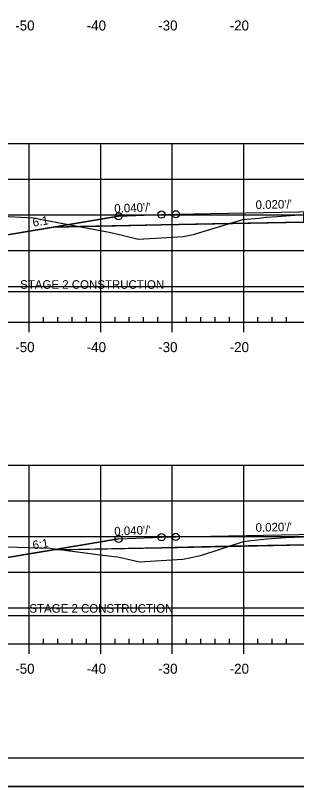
# Model space of a CAD drawing. Extents: x 1365647 to 1367999, y 387113 to 400173.
# Drawn here: x 1365842.2 to 1365881.5, y 387372.7 to 387480.6 of the extents above; entities that cross this region are included whole.
import ezdxf

# ---------------------------------------------------------------- set-up
doc = ezdxf.new("R2010")
doc.units = 0
for name, color, linetype in [('R_Alt Surface', 7, 'Continuous'), ('R_Axis', 7, 'Continuous'), ('R_Axis Annot', 7, 'Continuous'), ('R_Border', 7, 'Continuous'), ('R_Contours', 7, 'Continuous'), ('R_Exist Surface', 7, 'Continuous'), ('R_Fin Surface', 7, 'Continuous'), ('R_Fin Surface Annot', 7, 'Continuous'), ('R_Grid', 7, 'Continuous'), ('R_No Plot', 7, 'Continuous'), ('R_Proposed Const Limits', 7, 'Continuous'), ('R_Water', 7, 'Continuous')]:
    doc.layers.add(name, color=color, linetype=linetype)

msp = doc.modelspace()

# ---------------------------------------------------------------- linework, layer by layer
at = {"layer": 'R_Alt Surface'}
for points in [[(1365847.47, 387451.01), (1365862.59, 387451.32), (1365882.53, 387451.72), (1365882.53, 387453), (1365894.09, 387453.23), (1365906.15, 387452.99), (1365906.15, 387451.71), (1365925.59, 387451.32), (1365940.72, 387451.01)], [(1365847.47, 387405.86), (1365862.59, 387406.16), (1365882.72, 387406.56), (1365882.72, 387407.85), (1365894.09, 387408.08), (1365906.2, 387407.84), (1365906.2, 387406.55), (1365925.59, 387406.16), (1365940.72, 387405.86)]]:
    msp.add_lwpolyline(points, dxfattribs=at)
at = {"layer": 'R_Axis'}
for p, q in [((1365749.09, 387437.72), (1366039.09, 387437.72)), ((1365844.09, 387436.32), (1365844.09, 387437.72)), ((1365846.09, 387437.72), (1365846.09, 387438.42)), ((1365848.09, 387437.72), (1365848.09, 387438.42)), ((1365850.09, 387437.72), (1365850.09, 387438.42)), ((1365852.09, 387437.72), (1365852.09, 387438.42)), ((1365854.09, 387436.32), (1365854.09, 387437.72)), ((1365856.09, 387437.72), (1365856.09, 387438.42)), ((1365858.09, 387437.72), (1365858.09, 387438.42)), ((1365860.09, 387437.72), (1365860.09, 387438.42)), ((1365862.09, 387437.72), (1365862.09, 387438.42)), ((1365864.09, 387436.32), (1365864.09, 387437.72)), ((1365866.09, 387437.72), (1365866.09, 387438.42)), ((1365868.09, 387437.72), (1365868.09, 387438.42)), ((1365870.09, 387437.72), (1365870.09, 387438.42)), ((1365872.09, 387437.72), (1365872.09, 387438.42)), ((1365874.09, 387436.32), (1365874.09, 387437.72)), ((1365876.09, 387437.72), (1365876.09, 387438.42)), ((1365878.09, 387437.72), (1365878.09, 387438.42)), ((1365880.09, 387437.72), (1365880.09, 387438.42)), ((1365846.09, 387392.72), (1365846.09, 387393.42)), ((1365848.09, 387392.72), (1365848.09, 387393.42)), ((1365850.09, 387392.72), (1365850.09, 387393.42)), ((1365852.09, 387392.72), (1365852.09, 387393.42)), ((1365856.09, 387392.72), (1365856.09, 387393.42)), ((1365858.09, 387392.72), (1365858.09, 387393.42)), ((1365860.09, 387392.72), (1365860.09, 387393.42)), ((1365862.09, 387392.72), (1365862.09, 387393.42)), ((1365866.09, 387392.72), (1365866.09, 387393.42)), ((1365868.09, 387392.72), (1365868.09, 387393.42)), ((1365870.09, 387392.72), (1365870.09, 387393.42)), ((1365872.09, 387392.72), (1365872.09, 387393.42)), ((1365876.09, 387392.72), (1365876.09, 387393.42)), ((1365878.09, 387392.72), (1365878.09, 387393.42)), ((1365880.09, 387392.72), (1365880.09, 387393.42)), ((1365749.09, 387392.72), (1366039.09, 387392.72)), ((1365844.09, 387391.32), (1365844.09, 387392.72)), ((1365854.09, 387391.32), (1365854.09, 387392.72)), ((1365864.09, 387391.32), (1365864.09, 387392.72)), ((1365874.09, 387391.32), (1365874.09, 387392.72))]:
    msp.add_line(p, q, dxfattribs=at)
at = {"layer": 'R_Border'}
msp.add_line((1366052.27, 387376.72), (1365736.09, 387376.72), dxfattribs=at)
at = {"layer": 'R_Contours'}
for points in [[(1365872.13, 387451.51), (1365873.96, 387452.06), (1365876.25, 387452.28), (1365877.22, 387452.39), (1365878.77, 387452.49), (1365882.44, 387452.78), (1365882.53, 387452.78), (1365882.53, 387451.72)], [(1365824.59, 387452.2), (1365830.65, 387452.34), (1365833.44, 387452.49), (1365834.4, 387452.59), (1365841.21, 387452.51), (1365844.62, 387452.32), (1365846.82, 387451.9), (1365851.12, 387451.09), (1365847.47, 387451.01), (1365834.59, 387448.87)], [(1365851.12, 387451.09), (1365855.28, 387450.3), (1365857.08, 387449.86), (1365859.33, 387449.34), (1365863.34, 387449.57), (1365865.63, 387449.69), (1365867.25, 387450.03), (1365867.28, 387450.04), (1365867.33, 387450.05), (1365872.13, 387451.51), (1365862.59, 387451.32)], [(1365872.04, 387406.35), (1365874.05, 387407.01), (1365875.12, 387407.16), (1365877.33, 387407.4), (1365879.94, 387407.56), (1365882.36, 387407.68), (1365882.72, 387407.7), (1365882.72, 387406.56)], [(1365826.33, 387406.46), (1365831.54, 387406.34), (1365835.37, 387406.39), (1365837.51, 387406.45), (1365840.88, 387406.3), (1365847, 387406.09), (1365848.63, 387405.88), (1365847.47, 387405.86), (1365834.59, 387403.71)], [(1365848.63, 387405.88), (1365854.38, 387405.13), (1365856.43, 387404.87), (1365857.71, 387404.58), (1365859.51, 387404.18), (1365864.8, 387404.49), (1365865.59, 387404.53), (1365866.57, 387404.74), (1365868.18, 387405.09), (1365870.11, 387405.71), (1365872.04, 387406.35), (1365862.59, 387406.16)]]:
    msp.add_lwpolyline(points, close=True, dxfattribs=at)
at = {"layer": 'R_Exist Surface'}
for points in [[(1365841.21, 387452.51), (1365844.62, 387452.32), (1365846.82, 387451.9), (1365855.28, 387450.3), (1365857.08, 387449.86), (1365859.33, 387449.34), (1365863.34, 387449.57), (1365865.63, 387449.69), (1365867.25, 387450.03), (1365867.28, 387450.04), (1365867.33, 387450.05), (1365873.96, 387452.06), (1365876.25, 387452.28), (1365877.22, 387452.39), (1365878.77, 387452.49), (1365882.44, 387452.78)], [(1365840.88, 387406.3), (1365847, 387406.09), (1365854.38, 387405.13), (1365856.43, 387404.87), (1365857.71, 387404.58), (1365859.51, 387404.18), (1365864.8, 387404.49), (1365865.59, 387404.53), (1365866.57, 387404.74), (1365868.18, 387405.09), (1365870.11, 387405.71), (1365874.05, 387407.01), (1365875.12, 387407.16), (1365877.33, 387407.4), (1365879.94, 387407.56), (1365882.36, 387407.68)]]:
    msp.add_lwpolyline(points, dxfattribs=at)
at = {"layer": 'R_Fin Surface'}
for points in [[(1365824.59, 387452.2), (1365834.59, 387448.87), (1365847.47, 387451.01), (1365856.59, 387452.53), (1365862.59, 387452.77), (1365864.59, 387452.81), (1365894.09, 387453.4), (1365923.59, 387452.81), (1365925.59, 387452.77), (1365931.59, 387452.53), (1365940.72, 387451.01), (1365953.59, 387448.87), (1365959.49, 387450.83)], [(1365856.59, 387452.53), (1365862.59, 387452.77), (1365864.59, 387452.81), (1365894.09, 387453.4), (1365923.59, 387452.81), (1365925.59, 387452.77), (1365931.59, 387452.53)], [(1365826.33, 387406.46), (1365834.59, 387403.71), (1365847.47, 387405.86), (1365856.59, 387407.38), (1365862.59, 387407.62), (1365864.59, 387407.66), (1365894.09, 387408.25), (1365923.59, 387407.66), (1365925.59, 387407.62), (1365931.59, 387407.38), (1365940.72, 387405.86), (1365953.59, 387403.71), (1365958.26, 387405.27)], [(1365856.59, 387407.38), (1365862.59, 387407.62), (1365864.59, 387407.66), (1365894.09, 387408.25), (1365923.59, 387407.66), (1365925.59, 387407.62), (1365931.59, 387407.38)]]:
    msp.add_lwpolyline(points, dxfattribs=at)
at = {"layer": 'R_Grid'}
for p, q in [((1365749.09, 387462.72), (1366039.09, 387462.72)), ((1365844.09, 387437.72), (1365844.09, 387462.72)), ((1365854.09, 387437.72), (1365854.09, 387462.72)), ((1365864.09, 387437.72), (1365864.09, 387462.72)), ((1365874.09, 387437.72), (1365874.09, 387462.72)), ((1365749.09, 387457.72), (1366039.09, 387457.72)), ((1365749.09, 387452.72), (1366039.09, 387452.72)), ((1365749.09, 387447.72), (1366039.09, 387447.72)), ((1365749.09, 387442.72), (1366039.09, 387442.72)), ((1365749.09, 387437.72), (1366039.09, 387437.72)), ((1365749.09, 387417.72), (1366039.09, 387417.72)), ((1365844.09, 387392.72), (1365844.09, 387417.72)), ((1365854.09, 387392.72), (1365854.09, 387417.72)), ((1365864.09, 387392.72), (1365864.09, 387417.72)), ((1365874.09, 387392.72), (1365874.09, 387417.72)), ((1365749.09, 387412.72), (1366039.09, 387412.72)), ((1365749.09, 387407.72), (1366039.09, 387407.72)), ((1365749.09, 387402.72), (1366039.09, 387402.72)), ((1365749.09, 387397.72), (1366039.09, 387397.72)), ((1365749.09, 387392.72), (1366039.09, 387392.72))]:
    msp.add_line(p, q, dxfattribs=at)
at = {"layer": 'R_No Plot'}
msp.add_line((1365723.69, 387372.74), (1366057.03, 387372.74), dxfattribs=at)
msp.add_lwpolyline([(1365723.69, 387586.07), (1366057.03, 387586.07), (1366057.03, 387372.73), (1365723.69, 387372.73)], close=True, dxfattribs=at)
for centre in [(1365856.59, 387452.53), (1365856.59, 387452.53), (1365856.59, 387452.53), (1365856.59, 387452.53), (1365856.59, 387452.53), (1365862.59, 387452.77), (1365862.59, 387452.77), (1365862.59, 387452.77), (1365862.59, 387452.77), (1365862.59, 387452.77), (1365864.59, 387452.81), (1365864.59, 387452.81), (1365864.59, 387452.81), (1365864.59, 387452.81), (1365864.59, 387452.81), (1365856.59, 387407.38), (1365856.59, 387407.38), (1365856.59, 387407.38), (1365856.59, 387407.38), (1365856.59, 387407.38), (1365862.59, 387407.62), (1365862.59, 387407.62), (1365862.59, 387407.62), (1365862.59, 387407.62), (1365862.59, 387407.62), (1365864.59, 387407.66), (1365864.59, 387407.66), (1365864.59, 387407.66), (1365864.59, 387407.66), (1365864.59, 387407.66)]:
    msp.add_circle(centre, 0.5, dxfattribs=at)
at = {"layer": 'R_Proposed Const Limits'}
for points in [[(1365856.59, 387452.53), (1365834.59, 387448.87), (1365824.59, 387452.2)], [(1365856.59, 387407.38), (1365834.59, 387403.71), (1365826.33, 387406.46)]]:
    msp.add_lwpolyline(points, dxfattribs=at)
at = {"layer": 'R_Water'}
for p, q in [((1365824.59, 387441.99), (1365882.53, 387441.99)), ((1365826.33, 387396.66), (1365882.72, 387396.66))]:
    msp.add_line(p, q, dxfattribs=at)

# ---------------------------------------------------------------- texts
at = {"layer": 'R_Axis Annot'}
for s, p in [('-50', (1365842.13, 387478.52)), ('-40', (1365852.13, 387478.52)), ('-30', (1365862.13, 387478.52)), ('-20', (1365872.13, 387478.52)), ('-50', (1365842.13, 387433.52)), ('-40', (1365852.13, 387433.52)), ('-30', (1365862.13, 387433.52)), ('-20', (1365872.13, 387433.52)), ('-50', (1365842.13, 387388.52)), ('-40', (1365852.13, 387388.52)), ('-30', (1365862.13, 387388.52)), ('-20', (1365872.13, 387388.52))]:
    msp.add_text(s, height=1.4, dxfattribs=at).set_placement(p)
at = {"layer": 'R_Fin Surface Annot'}
for s, rotation, p in [("0.020'/'", 1.1458, (1365875.77, 387453.54)), ("0.020'/'", 1.1458, (1365875.77, 387453.54)), ("0.040'/'", 2.2906, (1365856.01, 387453.01)), ("0.040'/'", 2.2909, (1365856.01, 387453.01)), ('6:1', 9.4623, (1365844.66, 387451.05)), ('6:1', 9.4631, (1365844.66, 387451.05)), ("0.020'/'", 1.1458, (1365875.77, 387408.38)), ("0.020'/'", 1.1458, (1365875.77, 387408.38)), ("0.040'/'", 2.2906, (1365856.01, 387407.85)), ("0.040'/'", 2.2905, (1365856.01, 387407.85)), ('6:1', 9.4623, (1365844.66, 387405.9)), ('6:1', 9.4631, (1365844.66, 387405.9))]:
    msp.add_text(s, height=1.2, rotation=rotation, dxfattribs=at).set_placement(p)
at = {"layer": 'R_Water'}
for p in [(1365842.82, 387442.38), (1365844.11, 387397.06)]:
    msp.add_text('STAGE 2 CONSTRUCTION', height=1.2, dxfattribs=at).set_placement(p)

doc.saveas('drawing.dxf')
